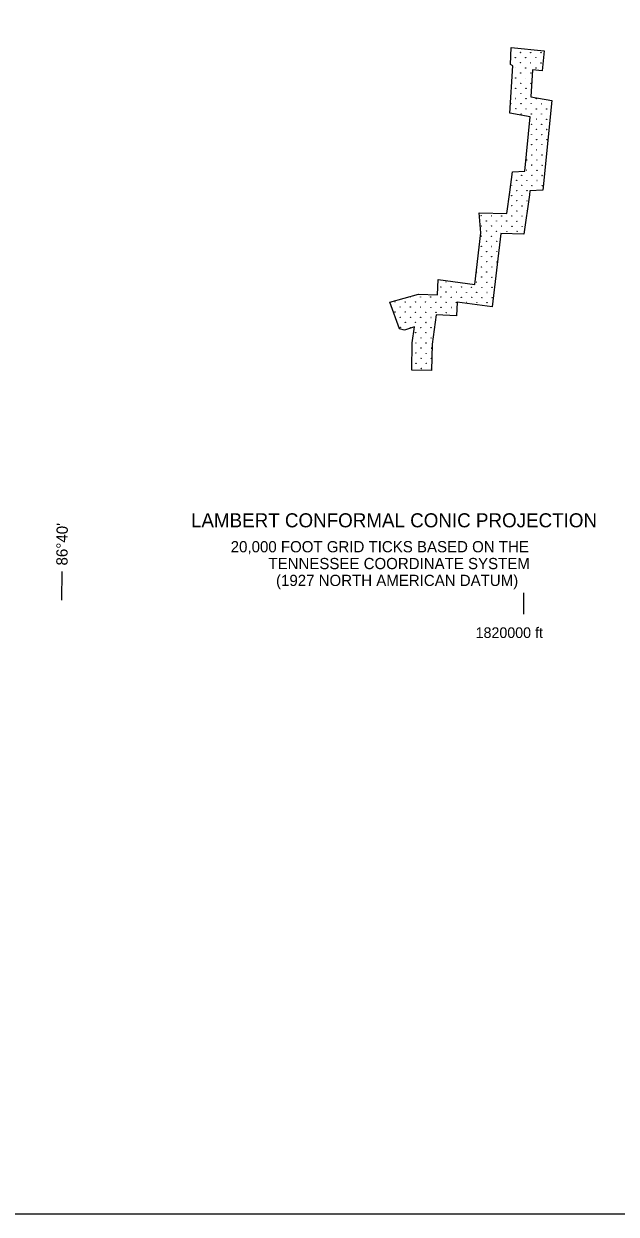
# Model space of a CAD drawing. Extents: x 1612280 to 1883141, y 560852 to 780851.
# Drawn here: x 1769718 to 1791978, y 560852 to 605620 of the extents above; entities that cross this region are included whole.
import ezdxf

# ---------------------------------------------------------------- set-up
doc = ezdxf.new("R2010")
doc.units = 0
for name, color, linetype in [('DESIGN - EROSION CONTROL - Devices', 7, 'Continuous'), ('DESIGN - SCRATCH - User 1', 7, 'Continuous'), ('SURVEY - DRAINAGE - Bridge Hydraulic Data - Points - Locators', 7, 'Continuous'), ('SURVEY - NON-TRANSPORTATION - Features - Points - Locators', 7, 'Continuous')]:
    doc.layers.add(name, color=color, linetype=linetype)

msp = doc.modelspace()

# ---------------------------------------------------------------- linework, layer by layer
at = {"layer": 'DESIGN - EROSION CONTROL - Devices'}
for centre in [(1788381, 604540), (1788381, 604540), (1788766, 604536), (1788766, 604536), (1789150, 604533), (1789150, 604533), (1788191, 604350), (1788191, 604350), (1788194, 603965), (1788194, 603965), (1788385, 604156), (1788385, 604156), (1788575, 604346), (1788575, 604346), (1788579, 603961), (1788579, 603961), (1788769, 604152), (1788769, 604152), (1788960, 604342), (1788960, 604342), (1788964, 603958), (1788964, 603958), (1789154, 604148), (1789154, 604148), (1788198, 603581), (1788198, 603581), (1788389, 603771), (1788389, 603771), (1788583, 603577), (1788583, 603577), (1788773, 603767), (1788773, 603767), (1788202, 603196), (1788202, 603196), (1788392, 603386), (1788392, 603386), (1788586, 603192), (1788586, 603192), (1788777, 603383), (1788777, 603383), (1788015, 602621), (1788015, 602621), (1788206, 602811), (1788206, 602811), (1788396, 603002), (1788396, 603002), (1788400, 602617), (1788400, 602617), (1788590, 602808), (1788590, 602808), (1788784, 602614), (1788784, 602614), (1788975, 602804), (1788975, 602804), (1789169, 602610), (1789169, 602610), (1788209, 602427), (1788209, 602427), (1788404, 602233), (1788404, 602233), (1788594, 602423), (1788594, 602423), (1788788, 602229), (1788788, 602229), (1788979, 602419), (1788979, 602419), (1789173, 602225), (1789173, 602225), (1789363, 602416), (1789363, 602416), (1788792, 601844), (1788792, 601844), (1788982, 602035), (1788982, 602035), (1789176, 601841), (1789176, 601841), (1789367, 602031), (1789367, 602031), (1788796, 601460), (1788796, 601460), (1788986, 601650), (1788986, 601650), (1788990, 601266), (1788990, 601266), (1789180, 601456), (1789180, 601456), (1789371, 601647), (1789371, 601647), (1789374, 601262), (1789374, 601262), (1788799, 601075), (1788799, 601075), (1788993, 600881), (1788993, 600881), (1789184, 601072), (1789184, 601072), (1788613, 600500), (1788613, 600500), (1788803, 600691), (1788803, 600691), (1788997, 600497), (1788997, 600497), (1789188, 600687), (1789188, 600687), (1788426, 599925), (1788426, 599925), (1788616, 600116), (1788616, 600116), (1788807, 600306), (1788807, 600306), (1788811, 599922), (1788811, 599922), (1789001, 600112), (1789001, 600112), (1789191, 600303), (1789191, 600303), (1789195, 599918), (1789195, 599918), (1788045, 599545), (1788045, 599545), (1788236, 599735), (1788236, 599735), (1788430, 599541), (1788430, 599541), (1788620, 599731), (1788620, 599731), (1788814, 599537), (1788814, 599537), (1789005, 599728), (1789005, 599728), (1789199, 599533), (1789199, 599533), (1788049, 599160), (1788049, 599160), (1788239, 599350), (1788239, 599350), (1788433, 599156), (1788433, 599156), (1788624, 599347), (1788624, 599347), (1788053, 598776), (1788053, 598776), (1788243, 598966), (1788243, 598966), (1788247, 598581), (1788247, 598581), (1788437, 598772), (1788437, 598772), (1788628, 598962), (1788628, 598962), (1786903, 598402), (1786903, 598402), (1787097, 598208), (1787097, 598208), (1787287, 598398), (1787287, 598398), (1787481, 598204), (1787481, 598204), (1787672, 598395), (1787672, 598395), (1787866, 598201), (1787866, 598201), (1788056, 598391), (1788056, 598391), (1788250, 598197), (1788250, 598197), (1788441, 598387), (1788441, 598387), (1786906, 598018), (1786906, 598018), (1787101, 597823), (1787101, 597823), (1787291, 598014), (1787291, 598014), (1787485, 597820), (1787485, 597820), (1787676, 598010), (1787676, 598010), (1787870, 597816), (1787870, 597816), (1788060, 598006), (1788060, 598006), (1788254, 597812), (1788254, 597812), (1788445, 598003), (1788445, 598003), (1786910, 597633), (1786910, 597633), (1786914, 597248), (1786914, 597248), (1787104, 597439), (1787104, 597439), (1787295, 597629), (1787295, 597629), (1787298, 597245), (1787298, 597245), (1787489, 597435), (1787489, 597435), (1786918, 596864), (1786918, 596864), (1787108, 597054), (1787108, 597054), (1787302, 596860), (1787302, 596860), (1787493, 597051), (1787493, 597051), (1786921, 596479), (1786921, 596479), (1787112, 596670), (1787112, 596670), (1787306, 596476), (1787306, 596476), (1787496, 596666), (1787496, 596666), (1785581, 595916), (1785581, 595916), (1786731, 596289), (1786731, 596289), (1786735, 595904), (1786735, 595904), (1786925, 596095), (1786925, 596095), (1787115, 596285), (1787115, 596285), (1787119, 595901), (1787119, 595901), (1787310, 596091), (1787310, 596091), (1785391, 595725), (1785391, 595725), (1785585, 595531), (1785585, 595531), (1785775, 595721), (1785775, 595721), (1785969, 595527), (1785969, 595527), (1786160, 595718), (1786160, 595718), (1786354, 595524), (1786354, 595524), (1786544, 595714), (1786544, 595714), (1786738, 595520), (1786738, 595520), (1786929, 595710), (1786929, 595710), (1787123, 595516), (1787123, 595516), (1787313, 595707), (1787313, 595707), (1783666, 595165), (1783666, 595165), (1783860, 594971), (1783860, 594971), (1784050, 595161), (1784050, 595161), (1784241, 595352), (1784241, 595352), (1784435, 595158), (1784435, 595158), (1784625, 595348), (1784625, 595348), (1784819, 595154), (1784819, 595154), (1785010, 595344), (1785010, 595344), (1785204, 595150), (1785204, 595150), (1785394, 595341), (1785394, 595341), (1785588, 595147), (1785588, 595147), (1785779, 595337), (1785779, 595337), (1785973, 595143), (1785973, 595143), (1786163, 595333), (1786163, 595333), (1786358, 595139), (1786358, 595139), (1786548, 595329), (1786548, 595329), (1786742, 595135), (1786742, 595135), (1786933, 595326), (1786933, 595326), (1787127, 595132), (1787127, 595132), (1787317, 595322), (1787317, 595322), (1783669, 594781), (1783669, 594781), (1783864, 594586), (1783864, 594586), (1784054, 594777), (1784054, 594777), (1784244, 594967), (1784244, 594967), (1784248, 594583), (1784248, 594583), (1784439, 594773), (1784439, 594773), (1784629, 594964), (1784629, 594964), (1784633, 594579), (1784633, 594579), (1784823, 594769), (1784823, 594769), (1785014, 594960), (1785014, 594960), (1785017, 594575), (1785017, 594575), (1785208, 594766), (1785208, 594766), (1785398, 594956), (1785398, 594956), (1785592, 594762), (1785592, 594762), (1785783, 594952), (1785783, 594952), (1783867, 594202), (1783867, 594202), (1784058, 594392), (1784058, 594392), (1784252, 594198), (1784252, 594198), (1784442, 594389), (1784442, 594389), (1784636, 594194), (1784636, 594194), (1784827, 594385), (1784827, 594385), (1785021, 594191), (1785021, 594191), (1784446, 594004), (1784446, 594004), (1784640, 593810), (1784640, 593810), (1784831, 594000), (1784831, 594000), (1785025, 593806), (1785025, 593806), (1784450, 593620), (1784450, 593620), (1784453, 593235), (1784453, 593235), (1784644, 593425), (1784644, 593425), (1784834, 593616), (1784834, 593616), (1784838, 593231), (1784838, 593231), (1785028, 593422), (1785028, 593422), (1784457, 592850), (1784457, 592850), (1784648, 593041), (1784648, 593041), (1784842, 592847), (1784842, 592847), (1785032, 593037), (1785032, 593037), (1784651, 592656), (1784651, 592656), (1785036, 592653), (1785036, 592653)]:
    msp.add_circle(centre, 5.28, dxfattribs=at)
for centre, start, end in [((1788781, 602998), 121.6369, 231.4813), ((1789378, 600877), 128.8764, 219.9957), ((1788631, 598578), 42.2014, 301.9585), ((1785966, 595912), 155.0811, 9.6051), ((1785977, 594758), 57.6378, 296.3393)]:
    msp.add_arc(centre, 5.28, start, end, dxfattribs=at)
at = {"layer": 'DESIGN - SCRATCH - User 1'}
msp.add_lwpolyline([(1612280, 780851), (1883141, 780851), (1883141, 560852), (1612280, 560852)], close=True, dxfattribs=at)
msp.add_lwpolyline([(1612280, 780851), (1883141, 780851), (1883141, 560852), (1612280, 560852)], close=True, dxfattribs=at)
for points in [[(1788741, 602117), (1787982, 602254), (1788089, 604036), (1788012, 604087), (1788027, 604735), (1789272, 604602), (1789192, 603857)], [(1788741, 602117), (1787982, 602254), (1788089, 604036), (1788012, 604087), (1788027, 604735), (1789272, 604602), (1789192, 603857)], [(1789192, 603857), (1788832, 603895), (1788770, 602874), (1789555, 602731)], [(1789192, 603857), (1788832, 603895), (1788770, 602874), (1789555, 602731)], [(1789555, 602731), (1789227, 599361), (1788739, 599335), (1788720, 599189)], [(1789555, 602731), (1789227, 599361), (1788739, 599335), (1788720, 599189)], [(1787976, 599289), (1788078, 600049), (1788543, 600075), (1788741, 602117)], [(1787976, 599289), (1788078, 600049), (1788543, 600075), (1788741, 602117)], [(1786834, 598513), (1787864, 598482), (1787976, 599289)], [(1786834, 598513), (1787864, 598482), (1787976, 599289)], [(1788719, 599186), (1788514, 597713), (1787648, 597738)], [(1788719, 599186), (1788514, 597713), (1787648, 597738)], [(1786661, 595820), (1786895, 597760), (1786834, 598513)], [(1786661, 595820), (1786895, 597760), (1786834, 598513)], [(1787648, 597738), (1787314, 594975)], [(1787648, 597738), (1787314, 594975)], [(1785263, 595422), (1785294, 596004)], [(1785263, 595422), (1785294, 596004)], [(1785294, 596004), (1786661, 595820)], [(1785294, 596004), (1786661, 595820)], [(1783478, 595156), (1784549, 595453), (1785263, 595422)], [(1783478, 595156), (1784549, 595453), (1785263, 595422)], [(1784396, 594227), (1784029, 594095), (1783835, 594146), (1783478, 595156)], [(1784396, 594227), (1784029, 594095), (1783835, 594146), (1783478, 595156)], [(1786000, 595152), (1785973, 594641)], [(1786000, 595152), (1785973, 594641)], [(1787314, 594975), (1786000, 595152)], [(1787314, 594975), (1786000, 595152)], [(1785213, 594673), (1785064, 593567), (1785044, 592579)], [(1785213, 594673), (1785064, 593567), (1785044, 592579)], [(1785973, 594641), (1785213, 594673)], [(1785973, 594641), (1785213, 594673)], [(1785044, 592579), (1784294, 592594), (1784315, 593625), (1784396, 594227)], [(1785044, 592579), (1784294, 592594), (1784315, 593625), (1784396, 594227)]]:
    msp.add_lwpolyline(points, dxfattribs=at)
at = {"layer": 'SURVEY - DRAINAGE - Bridge Hydraulic Data - Points - Locators'}
msp.add_line((1771147, 583950), (1771154, 585022), dxfattribs=at)
msp.add_line((1771147, 583950), (1771154, 585022), dxfattribs=at)
at = {"layer": 'SURVEY - NON-TRANSPORTATION - Features - Points - Locators'}
msp.add_line((1788504, 583422), (1788504, 584222), dxfattribs=at)
msp.add_line((1788504, 583422), (1788504, 584222), dxfattribs=at)

# ---------------------------------------------------------------- texts
at = {"layer": 'SURVEY - DRAINAGE - Bridge Hydraulic Data - Points - Locators'}
for s, height, rotation, p in [('LAMBERT CONFORMAL CONIC PROJECTION', 527.99, 0.0009, (1775999, 586684)), ('LAMBERT CONFORMAL CONIC PROJECTION', 527.99, 0.0009, (1775999, 586684)), ("86°40'", 425, 89.6097, (1771361, 585246)), ("86°40'", 425, 89.6097, (1771361, 585246)), ('20,000 FOOT GRID TICKS BASED ON THE', 422.39, 0.0009, (1777493, 585744)), ('20,000 FOOT GRID TICKS BASED ON THE', 422.39, 0.0009, (1777493, 585744)), ('TENNESSEE COORDINATE SYSTEM', 422.39, 0.0009, (1778910, 585111)), ('TENNESSEE COORDINATE SYSTEM', 422.39, 0.0009, (1778910, 585111)), ('(1927 NORTH AMERICAN DATUM)', 422.39, 0.0009, (1779196, 584477)), ('(1927 NORTH AMERICAN DATUM)', 422.39, 0.0009, (1779196, 584477))]:
    msp.add_text(s, height=height, rotation=rotation, dxfattribs=at).set_placement(p)
at = {"layer": 'SURVEY - NON-TRANSPORTATION - Features - Points - Locators'}
msp.add_text('1820000 ft', height=400, rotation=0, dxfattribs=at).set_placement((1786697, 582522))
msp.add_text('1820000 ft', height=400, rotation=0, dxfattribs=at).set_placement((1786697, 582522))

doc.saveas('drawing.dxf')
